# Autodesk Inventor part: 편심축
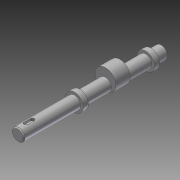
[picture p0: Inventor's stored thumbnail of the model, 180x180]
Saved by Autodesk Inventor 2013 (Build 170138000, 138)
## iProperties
Created: 2016-02
Part Number: 편심축
Material: 강철, 연강
Document SubType Name: Modeling
Designer: mduedu
Density: 1 g/cm^3
Author: mduedu
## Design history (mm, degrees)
sketch "스케치1"
  geometry: C1 r 6 at (0, 0); 1 further point
  constraints: 1 centre point, 1 coincident
  dimensions: "d0" = 12 diameter of C1
extrude "돌출1" new body sketch "스케치1" distance "d1" = 140; taper "d2" = 0 deg
chamfer "모따기1" distance "d3" = 1; stored, may be unused: second distance "d4" = 2, angle "d5" = 45 deg
node "작업 평면1"
sketch "스케치2"
  geometry: C1 r 10 at (0, 4); C2 r 6 at (0, 0) reference; 1 further point
  constraints: 1 centre point, 1 tangent, 1 vertical alignment
  dimensions: "d7" = 20 diameter of C1
extrude "돌출2" join sketch "스케치2" stored distance "d8" = 14; taper "d9" = 0 deg
node "작업 평면2"
sketch "스케치3"
  geometry: C1 r 8.5 at (0, 0); 1 further point
  constraints: 1 centre point, 1 coincident
  dimensions: "d12" = 17 diameter of C1
extrude "돌출3" join sketch "스케치3" distance "d13" = 5; taper "d14" = 0 deg
node "작업 평면3"
sketch "스케치4"
  geometry: L1 (-5, 140)-(5, 140) reference; L2 (0, 140)-(0, 0); L3 (-2, 132)-(-2, 126); L4 (2, 126)-(2, 132); A1 r 2 centre (0, 132) between (2, 132) and (-2, 132); A2 r 2 centre (0, 126) between (-2, 126) and (2, 126)
  constraints: 6 end point, 4 point on circle, 4 tangent, 2 centre point, 2 point on line, 1 midpoint, 1 parallel, 1 perpendicular
  dimensions: "d15" = 4 distance between parallel lines of L3 L4; "d17" = 6 distance edge to line of A1 L1; "d18" = 10 dimension on A2 A1
extrude "돌출4" cut sketch "스케치4" distance "d19" = 2.5; taper "d20" = 0 deg
sketch "스케치5"
  geometry: L1 (6, 55)-(6, 139) reference; L2 (-6, 55)-(-6, 139) reference; L3 (6, 115)-(-6, 115); L4 (-5, 140)-(5, 140) reference; L5 (6, 116.5)-(4.5, 115); L6 (6, 116.5)-(6, 115); L7 (4.5, 115)-(6, 115); 1 further point
  constraints: 8 end point, 4 point on line, 2 collinear, 1 perpendicular
  dimensions: "d21" = 25 distance between parallel lines of L3 L4; "d22" = 3 diameter of L5.start L3; "d24" = 45 deg angle of L3 L5
revolve "회전1" sketch "스케치5" stored, may be unused: angle "d25" = 90 deg
sketch "스케치6"
  geometry: L1 (6, 116.5)-(4.5, 115) reference; L2 (6, 113.5)-(4.5, 115) reference; 2 further points
  constraints: 1 coincident
node "작업 평면4"
sketch "스케치7"
  geometry: C1 r 8.5 at (0, -4); 1 further point
  constraints: 1 centre point, 1 coincident
  dimensions: "d27" = 17 diameter of C1
extrude "돌출5" join sketch "스케치7" distance "d29" = 5; taper "d30" = 0 deg
node "작업점1"
node "솔리드1"
other parameters: "d6" = -48, "d11" = -11
